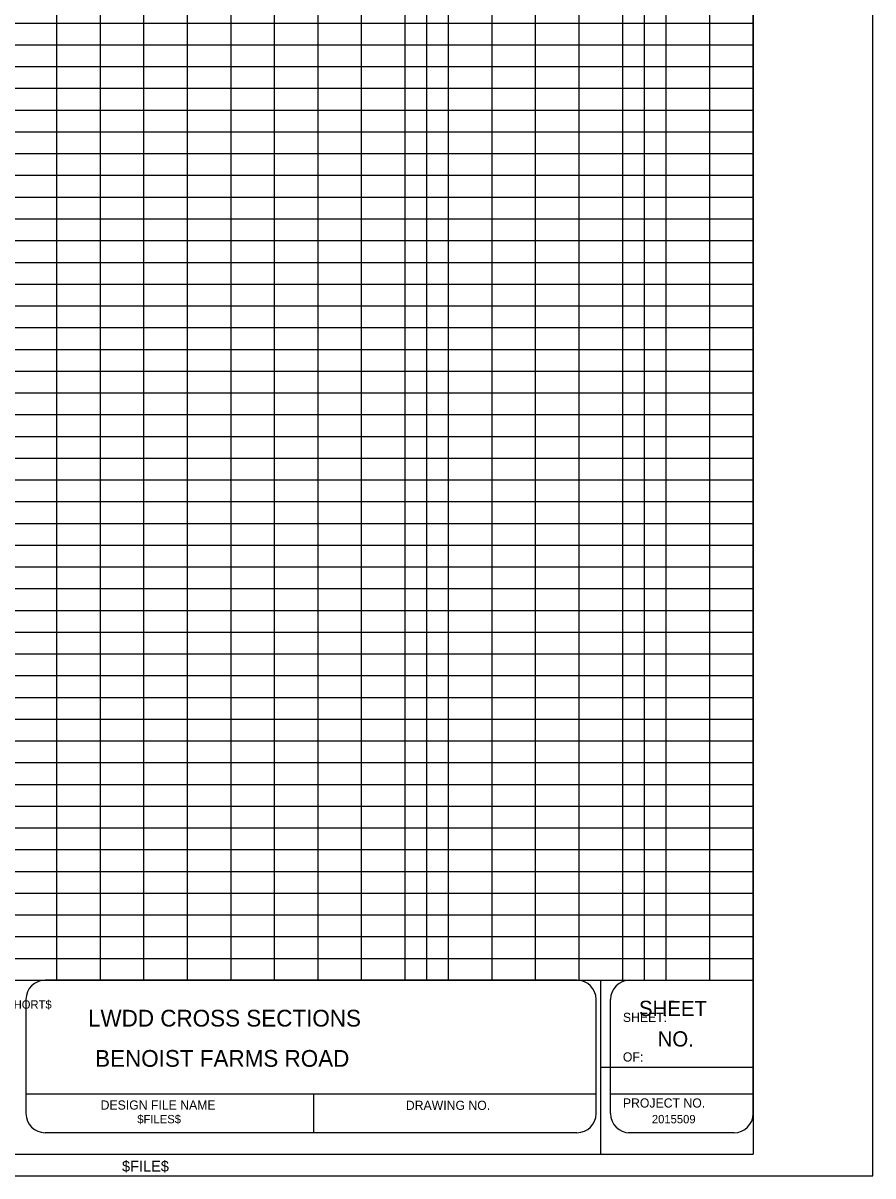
# Model space of a CAD drawing. Extents: x -0.7 to 16, y -0.9 to 9.7.
# Drawn here: x 12.04 to 15.95, y -0.9 to 4.4 of the extents above; entities that cross this region are included whole.
import ezdxf

# ---------------------------------------------------------------- set-up
doc = ezdxf.new("R2010")
doc.units = 0
for name, color, linetype in [('Default', 7, 'Continuous'), ('GridMaj_dp', 7, 'Continuous'), ('GridMinG_dp', 7, 'Continuous'), ('GridMinSub_dp', 7, 'Continuous'), ('PlotBorder_dp', 7, 'Continuous'), ('SheetBorder_dp', 7, 'Continuous'), ('SheetLines_dp', 7, 'Continuous'), ('TextMinor', 7, 'Continuous'), ('TextMisc', 7, 'Continuous')]:
    doc.layers.add(name, color=color, linetype=linetype)

msp = doc.modelspace()

# ---------------------------------------------------------------- linework, layer by layer
at = {"layer": 'Default'}
for p, q in [((15.4, -0.6133), (15.4, 9.5065)), ((0, 0), (15.4, 0)), ((14.5898, 0), (12.146, 0)), ((14.8324, 0), (15.4, 0)), ((12.0578, -0.0882), (12.0578, -0.6131)), ((14.678, -0.6135), (14.678, -0.0884)), ((14.7442, -0.6135), (14.7442, -0.0884)), ((14.6769, -0.5241), (12.0568, -0.5241)), ((13.3801, -0.7005), (13.3801, -0.5241)), ((15.4, -0.5241), (14.7475, -0.5241)), ((14.5898, -0.7014), (12.146, -0.7014)), ((15.3118, -0.7015), (14.8271, -0.7015))]:
    msp.add_line(p, q, dxfattribs=at)
for centre, major_axis, start_param, end_param in [((12.146, -0.0882), (0, 0.0882), 0, 1.570796), ((14.5898, -0.0884), (0, 0.0882), 4.712389, 6.283185), ((14.8324, -0.0884), (0, -0.0882), 3.141593, 4.712389), ((12.146, -0.6131), (0, -0.0882), 4.712389, 6.283185), ((14.5898, -0.6131), (0, 0.0882), 3.141593, 4.712389), ((14.8324, -0.6135), (0, -0.0882), 4.712389, 6.283185), ((15.3118, -0.6133), (0, -0.0882), 0, 1.570796)]:
    msp.add_ellipse(centre, major_axis=major_axis, ratio=0.999927, start_param=start_param, end_param=end_param, dxfattribs=at)
at = {"layer": 'GridMaj_dp'}
for p, q in [((13, 0), (13, 9.6)), ((13, 0), (13, 9.5999)), ((13.4, 0), (13.4, 9.6)), ((14, 0), (14, 9.6)), ((14.4, 0), (14.4, 9.6)), ((15, 0), (15, 9.6)), ((13.9, 0), (13.9, 9.4)), ((14.9, 0), (14.9, 9.4)), ((0, 4), (13.4, 4)), ((0, 4), (15.4, 4)), ((0, 3), (13.4, 3)), ((0, 3), (15.4, 3)), ((0, 2), (13.4, 2)), ((0, 2), (15.4, 2)), ((0, 1), (13.4, 1)), ((0, 1), (15.4, 1))]:
    msp.add_line(p, q, dxfattribs=at)
at = {"layer": 'GridMinG_dp'}
for p, q in [((0, 4.3), (15.4, 4.3)), ((0, 4.1), (15.4, 4.1)), ((0, 3.9), (15.4, 3.9)), ((0, 3.7), (15.4, 3.7)), ((0, 3.5), (15.4, 3.5)), ((0, 3.3), (15.4, 3.3)), ((0, 3.1), (15.4, 3.1)), ((0, 2.9), (15.4, 2.9)), ((0, 2.7), (15.4, 2.7)), ((0, 2.5), (15.4, 2.5)), ((0, 2.3), (15.4, 2.3)), ((0, 2.1), (15.4, 2.1)), ((0, 1.9), (15.4, 1.9)), ((0, 1.7), (15.4, 1.7)), ((0, 1.5), (15.4, 1.5)), ((0, 1.3), (15.4, 1.3)), ((0, 1.1), (15.4, 1.1)), ((0, 0.9), (15.4, 0.9)), ((0, 0.7), (15.4, 0.7)), ((0, 0.5), (15.4, 0.5)), ((0, 0.3), (15.4, 0.3)), ((0, 0.1), (15.4, 0.1))]:
    msp.add_line(p, q, dxfattribs=at)
at = {"layer": 'GridMinSub_dp'}
for p, q in [((12.2, 0), (12.2, 9.6)), ((12.2, 0), (12.2, 9.6)), ((12.4, 0), (12.4, 9.6)), ((12.4, 0), (12.4, 9.6)), ((12.6, 0), (12.6, 9.6)), ((12.6, 0), (12.6, 9.6)), ((12.8, 0), (12.8, 9.6)), ((12.8, 0), (12.8, 9.6)), ((13.2, 0), (13.2, 9.6)), ((13.2, 0), (13.2, 9.6)), ((13.4, 0), (13.4, 9.6)), ((13.6, 0), (13.6, 9.6)), ((13.8, 0), (13.8, 9.6)), ((14.2, 0), (14.2, 9.6)), ((14.4, 0), (14.4, 9.6)), ((14.6, 0), (14.6, 9.6)), ((14.8, 0), (14.8, 9.6)), ((15.2, 0), (15.2, 9.6)), ((0, 4.4), (15.4, 4.4)), ((0, 4.2), (13.4, 4.2)), ((0, 4.2), (15.4, 4.2)), ((0, 3.8), (13.4, 3.8)), ((0, 3.8), (15.4, 3.8)), ((0, 3.6), (13.4, 3.6)), ((0, 3.6), (15.4, 3.6)), ((0, 3.4), (13.4, 3.4)), ((0, 3.4), (15.4, 3.4)), ((0, 3.2), (13.4, 3.2)), ((0, 3.2), (15.4, 3.2)), ((0, 2.8), (13.4, 2.8)), ((0, 2.8), (15.4, 2.8)), ((0, 2.6), (13.4, 2.6)), ((0, 2.6), (15.4, 2.6)), ((0, 2.4), (13.4, 2.4)), ((0, 2.4), (15.4, 2.4)), ((0, 2.2), (13.4, 2.2)), ((0, 2.2), (15.4, 2.2)), ((0, 1.8), (13.4, 1.8)), ((0, 1.8), (15.4, 1.8)), ((0, 1.6), (13.4, 1.6)), ((0, 1.6), (15.4, 1.6)), ((0, 1.4), (13.4, 1.4)), ((0, 1.4), (15.4, 1.4)), ((0, 1.2), (13.4, 1.2)), ((0, 1.2), (15.4, 1.2)), ((0, 0.8), (13.4, 0.8)), ((0, 0.8), (15.4, 0.8)), ((0, 0.6), (13.4, 0.6)), ((0, 0.6), (15.4, 0.6)), ((0, 0.4), (13.4, 0.4)), ((0, 0.4), (15.4, 0.4)), ((0, 0.2), (13.4, 0.2)), ((0, 0.2), (15.4, 0.2))]:
    msp.add_line(p, q, dxfattribs=at)
at = {"layer": 'PlotBorder_dp'}
msp.add_lwpolyline([(-0.55, -0.9), (15.95, -0.9), (15.95, 9.7), (-0.55, 9.7)], close=True, dxfattribs=at)
msp.add_lwpolyline([(-0.55, -0.9), (15.95, -0.9), (15.95, 9.7), (-0.55, 9.7)], close=True, dxfattribs=at)
at = {"layer": 'SheetBorder_dp'}
for p, q in [((15.4, 9.6), (15.4, -0.8)), ((0, 0), (15.4, 0)), ((0, -0.8), (15.4, -0.8))]:
    msp.add_line(p, q, dxfattribs=at)
at = {"layer": 'SheetLines_dp'}
for p, q in [((14.7, -0.8), (14.7, 0)), ((14.7, -0.4), (15.4, -0.4))]:
    msp.add_line(p, q, dxfattribs=at)

# ---------------------------------------------------------------- texts
at = {"layer": 'Default'}
for s, height, p in [('$SCALESHORT$', 0.038546, (11.7691, -0.1311)), ('   LWDD CROSS SECTIONS    ', 0.077091, (12.2569, -0.2133)), ('SHEET:', 0.04207, (14.8009, -0.1922)), ('   BENOIST FARMS ROAD   ', 0.077091, (12.2895, -0.3982)), ('OF:', 0.04207, (14.8009, -0.374)), ('DESIGN FILE NAME', 0.042066, (12.4009, -0.5951)), ('DRAWING NO.', 0.042066, (13.8035, -0.5964)), ('PROJECT NO.', 0.042066, (14.8009, -0.5856)), ('$FILES$', 0.03855, (12.5694, -0.6581)), ('2015509', 0.03855, (14.9341, -0.6581))]:
    msp.add_text(s, height=height, dxfattribs=at).set_placement(p)
at = {"layer": 'TextMinor'}
msp.add_text('$FILE$', height=0.05, rotation=360, dxfattribs=at).set_placement((12.499, -0.8801))
at = {"layer": 'TextMisc'}
for s, p in [('SHEET', (14.8748, -0.1646)), ('NO.', (14.9605, -0.3048))]:
    msp.add_text(s, height=0.07, rotation=359.8607, dxfattribs=at).set_placement(p)

doc.saveas('drawing.dxf')
